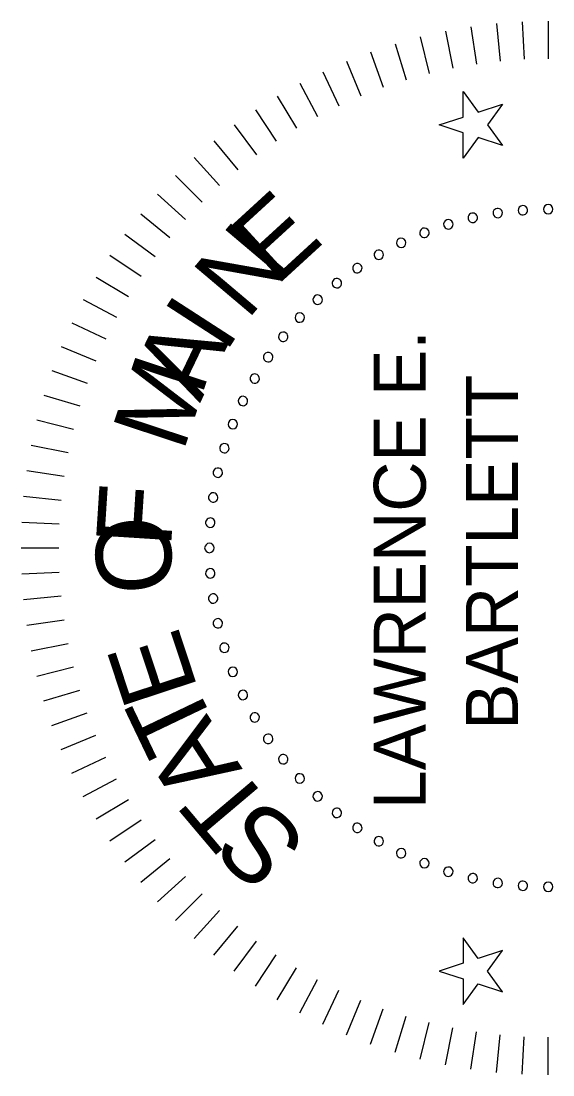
# Model space of a CAD drawing. Extents: x 916257 to 917115, y 329394 to 329944.
# Drawn here: x 917049.89 to 917069.98, y 329767.93 to 329807.76 of the extents above; entities that cross this region are included whole.
import ezdxf

# ---------------------------------------------------------------- set-up
doc = ezdxf.new("R2010")
doc.units = 0
doc.layers.add('Border', color=7, linetype='Continuous')
doc.layers.add('Default', color=7, linetype='Continuous')

# ---------------------------------------------------------------- blocks, each defined once
blk = doc.blocks.new('STAMP')
at = {"layer": 'Default'}
for p, q in [((-0.000781, 0.009427), (-0.000725, 0.008861)), ((-0.000391, 0.009455), (-0.000363, 0.008887)), ((0, 0.009465), (0, 0.008896)), ((0.000391, 0.009455), (0.000363, 0.008887)), ((0.000781, 0.009427), (0.000725, 0.008861)), ((-0.001554, 0.009312), (-0.001443, 0.008754)), ((-0.001169, 0.009379), (-0.001085, 0.008816)), ((0.001169, 0.009379), (0.001085, 0.008816)), ((0.001554, 0.009312), (0.001443, 0.008754)), ((-0.002312, 0.009122), (-0.002147, 0.008578)), ((-0.001935, 0.009226), (-0.001797, 0.008674)), ((0.001935, 0.009226), (0.001797, 0.008674)), ((0.002312, 0.009122), (0.002147, 0.008578)), ((-0.002683, 0.008999), (-0.002492, 0.008464)), ((0.002683, 0.008999), (0.002492, 0.008464)), ((-0.003048, 0.008859), (-0.00283, 0.008333)), ((0.003048, 0.008859), (0.00283, 0.008333)), ((-0.003406, 0.0087), (-0.003162, 0.008186)), ((0.003406, 0.0087), (0.003162, 0.008186)), ((-0.003755, 0.008525), (-0.003487, 0.008023)), ((0.003755, 0.008525), (0.003487, 0.008023)), ((-0.004095, 0.008332), (-0.003802, 0.007844)), ((0.004095, 0.008332), (0.003802, 0.007844)), ((-0.004425, 0.008123), (-0.004109, 0.00765)), ((0.004425, 0.008123), (0.004109, 0.00765)), ((-0.004745, 0.007898), (-0.004406, 0.007441)), ((0.004745, 0.007898), (0.004406, 0.007441)), ((-0.005053, 0.007657), (-0.004692, 0.007217)), ((0.005053, 0.007657), (0.004692, 0.007217)), ((-0.005349, 0.007402), (-0.004967, 0.00698)), ((0.005349, 0.007402), (0.004967, 0.00698)), ((-0.005632, 0.007132), (-0.00523, 0.00673)), ((0.005632, 0.007132), (0.00523, 0.00673)), ((-0.005902, 0.006849), (-0.00548, 0.006467)), ((0.005902, 0.006849), (0.00548, 0.006467)), ((-0.006157, 0.006553), (-0.005717, 0.006192)), ((0.006157, 0.006553), (0.005717, 0.006192)), ((-0.006398, 0.006245), (-0.005941, 0.005906)), ((0.006398, 0.006245), (0.005941, 0.005906)), ((-0.006623, 0.005925), (-0.00615, 0.005609)), ((0.006623, 0.005925), (0.00615, 0.005609)), ((-0.006832, 0.005595), (-0.006344, 0.005302)), ((0.006832, 0.005595), (0.006344, 0.005302)), ((-0.007025, 0.005255), (-0.006523, 0.004987)), ((0.007025, 0.005255), (0.006523, 0.004987)), ((-0.0072, 0.004906), (-0.006686, 0.004662)), ((0.0072, 0.004906), (0.006686, 0.004662)), ((-0.007359, 0.004548), (-0.006833, 0.00433)), ((0.007359, 0.004548), (0.006833, 0.00433)), ((-0.007499, 0.004183), (-0.006964, 0.003992)), ((0.007499, 0.004183), (0.006964, 0.003992)), ((-0.007622, 0.003812), (-0.007078, 0.003647)), ((0.007622, 0.003812), (0.007078, 0.003647)), ((-0.007726, 0.003435), (-0.007174, 0.003297)), ((0.007726, 0.003435), (0.007174, 0.003297)), ((-0.007812, 0.003054), (-0.007254, 0.002943)), ((-0.006396, 0.003148), (-0.006515, 0.002783)), ((-0.006278, 0.002783), (-0.006396, 0.003148)), ((0.006278, 0.002783), (0.006396, 0.003148)), ((0.006396, 0.003148), (0.006515, 0.002783)), ((0.007812, 0.003054), (0.007254, 0.002943)), ((-0.006515, 0.002783), (-0.006899, 0.002783)), ((-0.006899, 0.002783), (-0.006589, 0.002557)), ((-0.005894, 0.002783), (-0.006278, 0.002783)), ((-0.006204, 0.002557), (-0.005894, 0.002783)), ((0.006204, 0.002557), (0.005894, 0.002783)), ((0.005894, 0.002783), (0.006278, 0.002783)), ((0.006515, 0.002783), (0.006899, 0.002783)), ((0.006899, 0.002783), (0.006589, 0.002557)), ((-0.007879, 0.002669), (-0.007316, 0.002585)), ((-0.006589, 0.002557), (-0.006707, 0.002191)), ((-0.006086, 0.002191), (-0.006204, 0.002557)), ((0.006086, 0.002191), (0.006204, 0.002557)), ((0.006589, 0.002557), (0.006707, 0.002191)), ((0.007879, 0.002669), (0.007316, 0.002585)), ((-0.006707, 0.002191), (-0.006396, 0.002417)), ((-0.006396, 0.002417), (-0.006086, 0.002191)), ((0.006396, 0.002417), (0.006086, 0.002191)), ((0.006707, 0.002191), (0.006396, 0.002417)), ((-0.007927, 0.002281), (-0.007361, 0.002225)), ((0.007927, 0.002281), (0.007361, 0.002225)), ((-0.007955, 0.001891), (-0.007387, 0.001863)), ((0.007955, 0.001891), (0.007387, 0.001863)), ((-0.007965, 0.0015), (-0.007396, 0.0015)), ((0.007965, 0.0015), (0.007396, 0.0015))]:
    blk.add_line(p, q, dxfattribs=at)
for points in [[(-0.006278, 0.002783), (-0.006396, 0.003148), (-0.006515, 0.002783), (-0.006899, 0.002783), (-0.006589, 0.002557), (-0.006707, 0.002191), (-0.006396, 0.002417), (-0.006086, 0.002191), (-0.006204, 0.002557), (-0.005894, 0.002783)], [(0.006278, 0.002783), (0.006396, 0.003148), (0.006515, 0.002783), (0.006899, 0.002783), (0.006589, 0.002557), (0.006707, 0.002191), (0.006396, 0.002417), (0.006086, 0.002191), (0.006204, 0.002557), (0.005894, 0.002783)]]:
    blk.add_lwpolyline(points, close=True, dxfattribs=at)
for centre, start, end in [((0, 0.00662), 0, 180), ((-0.001139, 0.006492), 12.8571, 192.8571), ((-0.000763, 0.006563), 8.5714, 188.5714), ((-0.000763, 0.006563), 188.5714, 8.5714), ((-0.000383, 0.006606), 4.2857, 184.2857), ((-0.000383, 0.006606), 184.2857, 4.2857), ((0, 0.00662), 180, 0), ((0.000383, 0.006606), 355.7143, 175.7143), ((0.000383, 0.006606), 175.7143, 355.7143), ((0.000763, 0.006563), 171.4286, 351.4286), ((0.000763, 0.006563), 351.4286, 171.4286), ((0.001139, 0.006492), 347.1429, 167.1429), ((-0.001509, 0.006393), 17.1429, 197.1429), ((-0.001509, 0.006393), 197.1429, 17.1429), ((-0.001139, 0.006492), 192.8571, 12.8571), ((0.001139, 0.006492), 167.1429, 347.1429), ((0.001509, 0.006393), 162.8571, 342.8571), ((0.001509, 0.006393), 342.8571, 162.8571), ((-0.001871, 0.006266), 21.4286, 201.4286), ((-0.001871, 0.006266), 201.4286, 21.4286), ((0.001871, 0.006266), 158.5714, 338.5714), ((0.001871, 0.006266), 338.5714, 158.5714), ((-0.002222, 0.006113), 25.7143, 205.7143), ((-0.002222, 0.006113), 205.7143, 25.7143), ((0.002222, 0.006113), 154.2857, 334.2857), ((0.002222, 0.006113), 334.2857, 154.2857), ((-0.00256, 0.005934), 30, 210), ((-0.00256, 0.005934), 210, 30), ((0.00256, 0.005934), 150, 330), ((0.00256, 0.005934), 330, 150), ((-0.002884, 0.005731), 34.2857, 214.2857), ((-0.002884, 0.005731), 214.2857, 34.2857), ((0.002884, 0.005731), 145.7143, 325.7143), ((0.002884, 0.005731), 325.7143, 145.7143), ((-0.003193, 0.005503), 38.5714, 218.5714), ((-0.003193, 0.005503), 218.5714, 38.5714), ((0.003193, 0.005503), 141.4286, 321.4286), ((0.003193, 0.005503), 321.4286, 141.4286), ((-0.003483, 0.005254), 42.8571, 222.8571), ((-0.003483, 0.005254), 222.8571, 42.8571), ((0.003483, 0.005254), 137.1429, 317.1429), ((0.003483, 0.005254), 317.1429, 137.1429), ((-0.003754, 0.004983), 47.1429, 227.1429), ((-0.003754, 0.004983), 227.1429, 47.1429), ((0.003754, 0.004983), 132.8571, 312.8571), ((0.003754, 0.004983), 312.8571, 132.8571), ((-0.004003, 0.004693), 51.4286, 231.4286), ((-0.004003, 0.004693), 231.4286, 51.4286), ((0.004003, 0.004693), 128.5714, 308.5714), ((0.004003, 0.004693), 308.5714, 128.5714), ((-0.004231, 0.004384), 55.7143, 235.7143), ((-0.004231, 0.004384), 235.7143, 55.7143), ((0.004231, 0.004384), 124.2857, 304.2857), ((0.004231, 0.004384), 304.2857, 124.2857), ((-0.004434, 0.00406), 60, 240), ((-0.004434, 0.00406), 240, 60), ((0.004434, 0.00406), 120, 300), ((0.004434, 0.00406), 300, 120), ((-0.004613, 0.003722), 64.2857, 244.2857), ((-0.004613, 0.003722), 244.2857, 64.2857), ((0.004613, 0.003722), 115.7143, 295.7143), ((0.004613, 0.003722), 295.7143, 115.7143), ((-0.004766, 0.003371), 68.5714, 248.5714), ((-0.004766, 0.003371), 248.5714, 68.5714), ((0.004766, 0.003371), 111.4286, 291.4286), ((0.004766, 0.003371), 291.4286, 111.4286), ((-0.004893, 0.003009), 72.8571, 252.8571), ((-0.004893, 0.003009), 252.8571, 72.8571), ((0.004893, 0.003009), 107.1429, 287.1429), ((0.004893, 0.003009), 287.1429, 107.1429), ((-0.004992, 0.002639), 77.1429, 257.1429), ((-0.004992, 0.002639), 257.1429, 77.1429), ((0.004992, 0.002639), 102.8571, 282.8571), ((0.004992, 0.002639), 282.8571, 102.8571), ((-0.005063, 0.002263), 81.4286, 261.4286), ((-0.005063, 0.002263), 261.4286, 81.4286), ((0.005063, 0.002263), 98.5714, 278.5714), ((0.005063, 0.002263), 278.5714, 98.5714), ((-0.005106, 0.001883), 85.7143, 265.7143), ((-0.005106, 0.001883), 265.7143, 85.7143), ((0.005106, 0.001883), 94.2857, 274.2857), ((0.005106, 0.001883), 274.2857, 94.2857), ((-0.00512, 0.0015), 90, 270), ((-0.00512, 0.0015), 270, 90), ((0.00512, 0.0015), 90, 270), ((0.00512, 0.0015), 270, 90)]:
    blk.add_arc(centre, 0.0000711, start, end, dxfattribs=at)
for s, rotation, p in [('O', 3.6538, (-0.000663, 0.007159)), ('F', 356.3462, (-0.000007, 0.007201)), ('E', 18.2692, (-0.002136, 0.006786)), ('M', 341.7308, (0.001431, 0.007019)), ('T', 25.5769, (-0.002759, 0.006487)), ('A', 334.4231, (0.002185, 0.006762)), ('A', 32.8846, (-0.003342, 0.006114)), ('I', 327.1154, (0.002925, 0.006384)), ('T', 40.1923, (-0.003928, 0.005629)), ('N', 319.8077, (0.003426, 0.006054)), ('S', 47.5, (-0.004421, 0.005096)), ('E', 312.5, (0.003944, 0.005617))]:
    blk.add_text(s, height=0.001138, rotation=rotation, dxfattribs=at).set_placement(p)
for s, height, p in [('LAWRENCE E.', 0.00078513, (-0.003944, 0.00335)), ('BARTLETT', 0.0007851, (-0.002748, 0.001958))]:
    blk.add_text(s, height=height, dxfattribs=at).set_placement(p)

msp = doc.modelspace()

# ---------------------------------------------------------------- block references
at = {"layer": 'Border', "xscale": 2499.999999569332, "yscale": 2499.999999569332, "rotation": 90}
msp.add_blockref('STAMP', (917073.551, 329787.843), dxfattribs=at)

doc.saveas('drawing.dxf')
